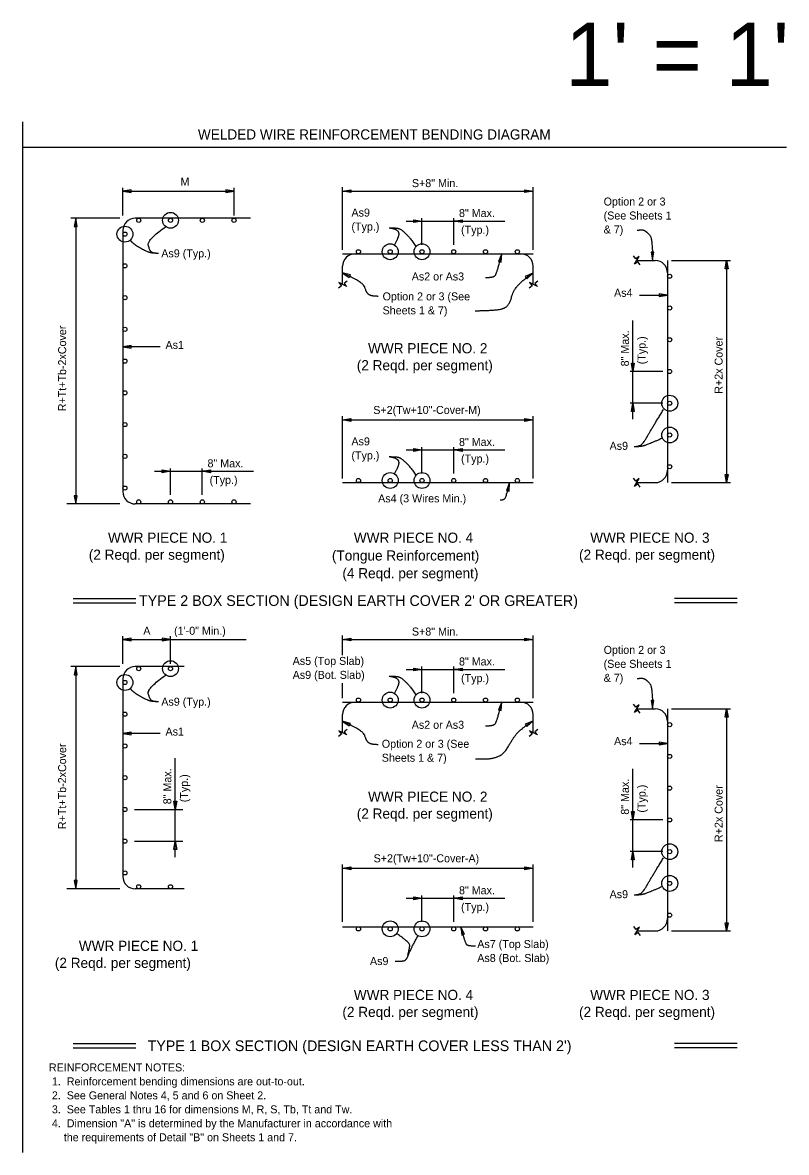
# Model space of a CAD drawing. Extents: x 10340.6 to 10376, y 76398.7 to 76415.8.
# Drawn here: x 10351.54 to 10361.15, y 76401.59 to 76415.83 of the extents above; entities that cross this region are included whole.
import ezdxf

# ---------------------------------------------------------------- set-up
doc = ezdxf.new("R2010")
doc.units = 0
for name, color, linetype in [('AdhocPoint_dp', 7, 'Continuous'), ('PlotBorder_dp', 7, 'Continuous'), ('Rebar', 7, 'Continuous'), ('Rebar_h', 7, 'Continuous'), ('Symbols', 7, 'Continuous')]:
    doc.layers.add(name, color=color, linetype=linetype)

msp = doc.modelspace()

# ---------------------------------------------------------------- linework, layer by layer
at = {"layer": 'PlotBorder_dp'}
for p, q in [((10351.539, 76414.577), (10351.539, 76401.592)), ((10351.539, 76414.259), (10361.155, 76414.259)), ((10352.801, 76413.398), (10352.801, 76413.745)), ((10352.801, 76413.703), (10354.201, 76413.703)), ((10354.201, 76413.398), (10354.201, 76413.745)), ((10355.567, 76412.965), (10355.567, 76413.754)), ((10355.567, 76413.703), (10357.967, 76413.703)), ((10357.967, 76412.965), (10357.967, 76413.754)), ((10352.763, 76413.362), (10352.146, 76413.362)), ((10352.208, 76413.362), (10352.208, 76409.762)), ((10356.567, 76413.029), (10356.567, 76413.361)), ((10356.967, 76413.029), (10356.967, 76413.361)), ((10356.367, 76413.326), (10357.611, 76413.326)), ((10357.068, 76413.326), (10356.967, 76413.326)), ((10359.71, 76412.831), (10360.453, 76412.831)), ((10360.402, 76412.831), (10360.402, 76410.031)), ((10359.307, 76412.392), (10359.66, 76412.392)), ((10359.222, 76410.83), (10359.222, 76412.074)), ((10353.272, 76411.743), (10352.801, 76411.743)), ((10359.222, 76411.531), (10359.222, 76411.431)), ((10359.598, 76411.431), (10359.188, 76411.431)), ((10359.598, 76411.031), (10359.188, 76411.031)), ((10355.567, 76410.081), (10355.567, 76410.87)), ((10355.567, 76410.82), (10357.967, 76410.82)), ((10357.967, 76410.081), (10357.967, 76410.87)), ((10356.367, 76410.443), (10357.611, 76410.443)), ((10356.567, 76410.145), (10356.567, 76410.478)), ((10356.967, 76410.145), (10356.967, 76410.478)), ((10357.068, 76410.443), (10356.967, 76410.443)), ((10353.201, 76410.174), (10354.445, 76410.174)), ((10353.401, 76409.876), (10353.401, 76410.209)), ((10353.801, 76409.876), (10353.801, 76410.209)), ((10353.902, 76410.174), (10353.801, 76410.174)), ((10359.71, 76410.031), (10360.453, 76410.031)), ((10352.763, 76409.762), (10352.096, 76409.762)), ((10352.175, 76408.571), (10352.963, 76408.571)), ((10352.175, 76408.517), (10352.963, 76408.517)), ((10360.535, 76408.571), (10359.748, 76408.571)), ((10360.535, 76408.517), (10359.748, 76408.517)), ((10352.801, 76407.749), (10352.801, 76408.095)), ((10353.401, 76407.749), (10353.401, 76408.095)), ((10355.567, 76407.855), (10355.567, 76408.104)), ((10357.967, 76407.316), (10357.967, 76408.104)), ((10352.801, 76408.054), (10354.354, 76408.054)), ((10355.567, 76408.054), (10357.967, 76408.054)), ((10352.763, 76407.713), (10352.146, 76407.713)), ((10352.208, 76407.713), (10352.208, 76404.913)), ((10356.367, 76407.677), (10357.611, 76407.677)), ((10356.567, 76407.379), (10356.567, 76407.712)), ((10356.967, 76407.379), (10356.967, 76407.712)), ((10357.068, 76407.677), (10356.967, 76407.677)), ((10355.567, 76407.316), (10355.567, 76407.505)), ((10359.71, 76407.181), (10360.453, 76407.181)), ((10360.402, 76407.181), (10360.402, 76404.382)), ((10353.272, 76406.87), (10352.801, 76406.87)), ((10359.307, 76406.743), (10359.66, 76406.743)), ((10353.461, 76405.312), (10353.461, 76406.557)), ((10359.222, 76405.181), (10359.222, 76406.425)), ((10353.461, 76406.014), (10353.461, 76405.913)), ((10352.949, 76405.913), (10353.555, 76405.913)), ((10359.222, 76405.882), (10359.222, 76405.781)), ((10359.598, 76405.781), (10359.188, 76405.781)), ((10352.949, 76405.513), (10353.555, 76405.513)), ((10359.598, 76405.381), (10359.188, 76405.381)), ((10355.567, 76404.495), (10355.567, 76405.221)), ((10355.567, 76405.171), (10357.967, 76405.171)), ((10357.967, 76404.495), (10357.967, 76405.221)), ((10352.763, 76404.913), (10352.096, 76404.913)), ((10356.567, 76404.496), (10356.567, 76404.828)), ((10356.967, 76404.496), (10356.967, 76404.828)), ((10356.367, 76404.794), (10357.611, 76404.794)), ((10357.068, 76404.794), (10356.967, 76404.794)), ((10359.71, 76404.382), (10360.453, 76404.382)), ((10352.175, 76402.962), (10352.963, 76402.962)), ((10360.535, 76402.962), (10359.748, 76402.962)), ((10352.175, 76402.908), (10352.963, 76402.908)), ((10360.535, 76402.908), (10359.748, 76402.908))]:
    msp.add_line(p, q, dxfattribs=at)
for points in [[(10352.801, 76413.703), (10352.905, 76413.686), (10352.905, 76413.721)], [(10354.201, 76413.703), (10354.097, 76413.721), (10354.097, 76413.686)], [(10355.671, 76413.686), (10355.567, 76413.703), (10355.671, 76413.721)], [(10357.863, 76413.721), (10357.967, 76413.703), (10357.863, 76413.686)], [(10352.208, 76413.362), (10352.19, 76413.258), (10352.225, 76413.258)], [(10356.463, 76413.344), (10356.567, 76413.326), (10356.463, 76413.309)], [(10357.071, 76413.309), (10356.967, 76413.326), (10357.071, 76413.344)], [(10357.574, 76412.916), (10357.531, 76412.819), (10357.565, 76412.81)], [(10359.469, 76412.832), (10359.486, 76412.936), (10359.451, 76412.936)], [(10360.385, 76412.726), (10360.402, 76412.831), (10360.42, 76412.726)], [(10355.563, 76412.673), (10355.651, 76412.614), (10355.665, 76412.647)], [(10357.961, 76412.672), (10357.866, 76412.627), (10357.886, 76412.598)], [(10359.66, 76412.392), (10359.555, 76412.41), (10359.555, 76412.375)], [(10352.801, 76411.743), (10352.905, 76411.725), (10352.905, 76411.76)], [(10359.24, 76411.535), (10359.222, 76411.431), (10359.205, 76411.535)], [(10359.205, 76410.926), (10359.222, 76411.031), (10359.24, 76410.926)], [(10355.671, 76410.802), (10355.567, 76410.82), (10355.671, 76410.838)], [(10357.863, 76410.838), (10357.967, 76410.82), (10357.863, 76410.802)], [(10356.463, 76410.461), (10356.567, 76410.443), (10356.463, 76410.425)], [(10357.071, 76410.425), (10356.967, 76410.443), (10357.071, 76410.461)], [(10353.297, 76410.191), (10353.401, 76410.174), (10353.297, 76410.156)], [(10353.905, 76410.156), (10353.801, 76410.174), (10353.905, 76410.191)], [(10360.42, 76410.135), (10360.402, 76410.031), (10360.385, 76410.135)], [(10357.668, 76410.03), (10357.629, 76409.932), (10357.663, 76409.924)], [(10352.208, 76409.762), (10352.225, 76409.866), (10352.19, 76409.866)], [(10352.801, 76408.054), (10352.905, 76408.036), (10352.905, 76408.072)], [(10353.401, 76408.054), (10353.297, 76408.072), (10353.297, 76408.036)], [(10355.671, 76408.036), (10355.567, 76408.054), (10355.671, 76408.072)], [(10357.863, 76408.072), (10357.967, 76408.054), (10357.863, 76408.036)], [(10352.208, 76407.713), (10352.19, 76407.609), (10352.225, 76407.609)], [(10356.463, 76407.695), (10356.567, 76407.677), (10356.463, 76407.659)], [(10357.071, 76407.659), (10356.967, 76407.677), (10357.071, 76407.695)], [(10357.574, 76407.267), (10357.531, 76407.17), (10357.565, 76407.161)], [(10359.469, 76407.183), (10359.486, 76407.287), (10359.451, 76407.287)], [(10360.385, 76407.077), (10360.402, 76407.181), (10360.42, 76407.077)], [(10355.563, 76407.024), (10355.651, 76406.965), (10355.665, 76406.997)], [(10357.964, 76407.027), (10357.867, 76406.986), (10357.886, 76406.956)], [(10352.801, 76406.87), (10352.905, 76406.853), (10352.905, 76406.888)], [(10359.66, 76406.743), (10359.555, 76406.761), (10359.555, 76406.726)], [(10353.479, 76406.017), (10353.461, 76405.913), (10353.444, 76406.017)], [(10359.24, 76405.886), (10359.222, 76405.781), (10359.205, 76405.886)], [(10353.444, 76405.409), (10353.461, 76405.513), (10353.479, 76405.409)], [(10359.205, 76405.277), (10359.222, 76405.381), (10359.24, 76405.277)], [(10355.671, 76405.153), (10355.567, 76405.171), (10355.671, 76405.188)], [(10357.863, 76405.188), (10357.967, 76405.171), (10357.863, 76405.153)], [(10352.208, 76404.913), (10352.225, 76405.017), (10352.19, 76405.017)], [(10356.463, 76404.811), (10356.567, 76404.794), (10356.463, 76404.776)], [(10357.071, 76404.776), (10356.967, 76404.794), (10357.071, 76404.811)], [(10357.054, 76404.435), (10357.067, 76404.33), (10357.101, 76404.34)], [(10360.42, 76404.486), (10360.402, 76404.382), (10360.385, 76404.486)]]:
    msp.add_lwpolyline(points, close=True, dxfattribs=at)
for centre in [(10353.401, 76413.336), (10352.827, 76413.162), (10356.167, 76412.94), (10356.567, 76412.94), (10359.686, 76411.031), (10359.686, 76410.631), (10356.167, 76410.057), (10356.567, 76410.057), (10353.401, 76407.687), (10352.827, 76407.513), (10356.167, 76407.291), (10356.567, 76407.291), (10359.686, 76405.381), (10359.686, 76404.981), (10356.167, 76404.408), (10356.567, 76404.408)]:
    msp.add_circle(centre, 0.1, dxfattribs=at)
for points in [[(10353.249, 76412.919), (10353.177, 76412.919), (10353.137, 76412.959), (10353.106, 76413.086), (10353.336, 76413.255)], [(10356.155, 76413.241), (10356.232, 76413.23), (10356.28, 76413.184), (10356.265, 76413.108), (10356.221, 76413.028)], [(10356.155, 76413.241), (10356.242, 76413.241), (10356.297, 76413.228), (10356.415, 76413.122), (10356.488, 76413.007)], [(10359.278, 76413.21), (10359.344, 76413.224), (10359.406, 76413.183), (10359.469, 76413.108), (10359.469, 76412.832)], [(10353.249, 76412.919), (10353.177, 76412.919), (10353.09, 76412.944), (10352.923, 76413.044), (10352.895, 76413.087)], [(10357.366, 76412.615), (10357.466, 76412.615), (10357.51, 76412.665), (10357.574, 76412.916)], [(10356.014, 76412.378), (10355.914, 76412.378), (10355.859, 76412.443), (10355.83, 76412.554), (10355.563, 76412.673)], [(10357.238, 76412.197), (10357.383, 76412.197), (10357.593, 76412.216), (10357.674, 76412.284), (10357.734, 76412.514), (10357.961, 76412.672)], [(10359.239, 76410.486), (10359.27, 76410.486), (10359.348, 76410.509), (10359.487, 76410.761), (10359.609, 76410.951)], [(10359.239, 76410.486), (10359.322, 76410.486), (10359.415, 76410.514), (10359.586, 76410.59)], [(10356.155, 76410.358), (10356.242, 76410.358), (10356.297, 76410.344), (10356.415, 76410.239), (10356.488, 76410.124)], [(10356.155, 76410.358), (10356.232, 76410.346), (10356.28, 76410.301), (10356.265, 76410.225), (10356.221, 76410.145)], [(10357.551, 76409.812), (10357.596, 76409.812), (10357.631, 76409.857), (10357.668, 76410.03)], [(10353.249, 76407.27), (10353.177, 76407.27), (10353.137, 76407.31), (10353.106, 76407.436), (10353.336, 76407.606)], [(10356.155, 76407.592), (10356.232, 76407.581), (10356.28, 76407.535), (10356.265, 76407.459), (10356.221, 76407.379)], [(10356.155, 76407.592), (10356.242, 76407.592), (10356.297, 76407.579), (10356.415, 76407.473), (10356.488, 76407.358)], [(10359.278, 76407.561), (10359.344, 76407.575), (10359.406, 76407.534), (10359.469, 76407.459), (10359.469, 76407.183)], [(10353.249, 76407.27), (10353.177, 76407.27), (10353.09, 76407.295), (10352.923, 76407.395), (10352.895, 76407.438)], [(10357.366, 76406.966), (10357.466, 76406.966), (10357.51, 76407.016), (10357.574, 76407.267)], [(10356.014, 76406.729), (10355.914, 76406.729), (10355.859, 76406.794), (10355.83, 76406.905), (10355.563, 76407.024)], [(10357.24, 76406.552), (10357.337, 76406.552), (10357.455, 76406.552), (10357.605, 76406.615), (10357.703, 76406.795), (10357.805, 76406.926), (10357.964, 76407.027)], [(10359.239, 76404.837), (10359.27, 76404.837), (10359.348, 76404.86), (10359.487, 76405.112), (10359.609, 76405.302)], [(10359.239, 76404.837), (10359.322, 76404.837), (10359.415, 76404.865), (10359.586, 76404.941)], [(10357.24, 76404.191), (10357.16, 76404.191), (10357.123, 76404.21), (10357.081, 76404.345), (10357.054, 76404.435)], [(10356.23, 76404), (10356.306, 76404), (10356.372, 76404.013), (10356.417, 76404.14), (10356.516, 76404.322)], [(10356.388, 76404.075), (10356.413, 76404.167), (10356.413, 76404.235), (10356.252, 76404.347)]]:
    msp.add_open_spline(points, degree=2, dxfattribs=at)
at = {"layer": 'Rebar'}
for p, q in [((10354.408, 76413.362), (10352.957, 76413.362)), ((10352.801, 76413.206), (10352.801, 76409.918)), ((10355.567, 76412.914), (10357.967, 76412.914)), ((10359.66, 76412.831), (10359.66, 76410.031)), ((10355.567, 76410.031), (10357.967, 76410.031)), ((10354.408, 76409.762), (10352.957, 76409.762)), ((10353.573, 76407.713), (10352.957, 76407.713)), ((10352.801, 76407.557), (10352.801, 76405.069)), ((10355.567, 76407.265), (10357.967, 76407.265)), ((10359.66, 76407.181), (10359.66, 76404.382)), ((10353.573, 76404.913), (10352.957, 76404.913)), ((10355.567, 76404.434), (10357.967, 76404.434))]:
    msp.add_line(p, q, dxfattribs=at)
for centre in [(10353.001, 76413.336), (10353.401, 76413.336), (10353.801, 76413.336), (10354.201, 76413.336), (10352.827, 76413.162), (10355.767, 76412.94), (10356.167, 76412.94), (10356.567, 76412.94), (10356.967, 76412.94), (10357.367, 76412.94), (10357.767, 76412.94), (10352.827, 76412.762), (10359.686, 76412.631), (10352.827, 76412.362), (10359.686, 76412.231), (10352.827, 76411.962), (10359.686, 76411.831), (10352.827, 76411.562), (10359.686, 76411.431), (10352.827, 76411.162), (10359.686, 76411.031), (10352.827, 76410.762), (10359.686, 76410.631), (10352.827, 76410.362), (10359.686, 76410.231), (10355.767, 76410.057), (10356.167, 76410.057), (10356.567, 76410.057), (10356.967, 76410.057), (10357.367, 76410.057), (10357.767, 76410.057), (10352.827, 76409.962), (10352.827, 76409.962), (10353.001, 76409.788), (10353.401, 76409.788), (10353.801, 76409.788), (10354.201, 76409.788), (10353.001, 76407.687), (10353.401, 76407.687), (10352.827, 76407.513), (10355.767, 76407.291), (10356.167, 76407.291), (10356.567, 76407.291), (10356.967, 76407.291), (10357.367, 76407.291), (10357.767, 76407.291), (10352.827, 76407.113), (10359.686, 76406.981), (10352.827, 76406.713), (10359.686, 76406.581), (10352.827, 76406.313), (10359.686, 76406.181), (10352.827, 76405.913), (10359.686, 76405.781), (10352.827, 76405.513), (10359.686, 76405.381), (10352.827, 76405.113), (10353.001, 76404.939), (10353.401, 76404.939), (10359.686, 76404.981), (10359.686, 76404.581), (10355.767, 76404.408), (10356.167, 76404.408), (10356.567, 76404.408), (10356.967, 76404.408), (10357.367, 76404.408), (10357.767, 76404.408)]:
    msp.add_circle(centre, 0.026, dxfattribs=at)
for centre, start, end in [((10352.957, 76413.206), 90, 180), ((10352.957, 76409.918), 180, 270), ((10352.957, 76407.557), 90, 180), ((10352.957, 76405.069), 180, 270)]:
    msp.add_arc(centre, 0.156, start, end, dxfattribs=at)
at = {"layer": 'Rebar_h'}
for p, q in [((10359.277, 76412.831), (10359.503, 76412.831)), ((10355.567, 76412.531), (10355.567, 76412.758)), ((10357.967, 76412.531), (10357.967, 76412.758)), ((10359.277, 76410.031), (10359.503, 76410.031)), ((10355.567, 76406.882), (10355.567, 76407.109)), ((10357.967, 76406.882), (10357.967, 76407.109)), ((10359.277, 76407.181), (10359.503, 76407.181)), ((10359.277, 76404.382), (10359.503, 76404.382))]:
    msp.add_line(p, q, dxfattribs=at)
for centre, start, end in [((10355.724, 76412.758), 90, 180), ((10357.811, 76412.758), 0, 90), ((10359.503, 76412.674), 360, 90), ((10359.503, 76410.187), 270, 360), ((10355.724, 76407.109), 90, 180), ((10357.811, 76407.109), 0, 90), ((10359.503, 76407.025), 360, 90), ((10359.503, 76404.538), 270, 360)]:
    msp.add_arc(centre, 0.156, start, end, dxfattribs=at)
at = {"layer": 'Symbols'}
for points in [[(10359.313, 76412.774), (10359.285, 76412.813), (10359.243, 76412.783), (10359.3, 76412.88), (10359.258, 76412.85), (10359.23, 76412.889)], [(10355.625, 76412.571), (10355.588, 76412.54), (10355.62, 76412.5), (10355.52, 76412.552), (10355.553, 76412.512), (10355.515, 76412.482)], [(10358.025, 76412.571), (10357.988, 76412.54), (10358.02, 76412.5), (10357.92, 76412.552), (10357.953, 76412.512), (10357.915, 76412.482)], [(10359.313, 76409.975), (10359.285, 76410.014), (10359.243, 76409.983), (10359.3, 76410.081), (10359.258, 76410.05), (10359.23, 76410.089)], [(10359.313, 76407.125), (10359.285, 76407.164), (10359.243, 76407.134), (10359.3, 76407.231), (10359.258, 76407.201), (10359.23, 76407.24)], [(10355.625, 76406.921), (10355.588, 76406.891), (10355.62, 76406.851), (10355.52, 76406.903), (10355.553, 76406.863), (10355.515, 76406.832)], [(10358.025, 76406.921), (10357.988, 76406.891), (10358.02, 76406.851), (10357.92, 76406.903), (10357.953, 76406.863), (10357.915, 76406.832)], [(10359.319, 76404.325), (10359.29, 76404.364), (10359.248, 76404.333), (10359.305, 76404.431), (10359.263, 76404.4), (10359.235, 76404.439)]]:
    msp.add_lwpolyline(points, dxfattribs=at)

# ---------------------------------------------------------------- texts
at = {"layer": 'AdhocPoint_dp'}
for s, height, p in [("1' = 1'", 0.8, (10358.371, 76415.027)), ('WELDED WIRE REINFORCEMENT BENDING DIAGRAM', 0.128, (10353.746, 76414.354)), ('M', 0.101, (10353.526, 76413.773)), ('Option 2 or 3 ', 0.1008, (10358.854, 76413.522)), ('As9', 0.1008, (10355.679, 76413.383)), ('(See Sheets 1 ', 0.1008, (10358.854, 76413.346)), ('(Typ.)', 0.1008, (10355.679, 76413.207)), ('(Typ.)', 0.1008, (10357.059, 76413.166)), ('& 7)', 0.1008, (10358.854, 76413.17)), ('As9 (Typ.)', 0.1008, (10353.285, 76412.869)), ('As2 or As3', 0.1008, (10356.438, 76412.578)), ('Option 2 or 3 (See ', 0.1008, (10356.071, 76412.327)), ('As4', 0.1008, (10358.985, 76412.372)), ('Sheets 1 & 7)', 0.1008, (10356.071, 76412.151)), ('As1', 0.1008, (10353.338, 76411.716)), ('WWR PIECE NO. 2', 0.128, (10355.888, 76411.66)), ('(2 Reqd. per segment)', 0.128, (10355.746, 76411.446)), ('As9', 0.1008, (10355.679, 76410.5)), ('As9', 0.1008, (10358.929, 76410.444)), ('(Typ.)', 0.1008, (10355.679, 76410.324)), ('(Typ.)', 0.1008, (10357.059, 76410.283)), ('(Typ.)', 0.1008, (10353.893, 76410.014)), ('As4 (3 Wires Min.)', 0.1008, (10356.015, 76409.782)), ('WWR PIECE NO. 1', 0.128, (10352.614, 76409.273)), ('WWR PIECE NO. 4', 0.128, (10355.709, 76409.273)), ('WWR PIECE NO. 3', 0.128, (10358.685, 76409.273)), ('(2 Reqd. per segment)', 0.128, (10352.372, 76409.059)), ('(Tongue Reinforcement)', 0.128, (10355.433, 76409.049)), ('(2 Reqd. per segment)', 0.128, (10358.544, 76409.059)), ('(4 Reqd. per segment)', 0.128, (10355.565, 76408.826)), ("TYPE 2 BOX SECTION (DESIGN EARTH COVER 2' OR GREATER)", 0.1344, (10353.004, 76408.477)), ('(1\'-0" Min.)', 0.1008, (10353.446, 76408.114)), ('A', 0.101, (10353.058, 76408.114)), ('Option 2 or 3 ', 0.1008, (10358.854, 76407.873)), ('As5 (Top Slab)', 0.1008, (10354.939, 76407.734)), ('(See Sheets 1 ', 0.1008, (10358.854, 76407.697)), ('As9 (Bot. Slab)', 0.1008, (10354.939, 76407.558)), ('(Typ.)', 0.1008, (10357.059, 76407.517)), ('& 7)', 0.1008, (10358.854, 76407.521)), ('As9 (Typ.)', 0.1008, (10353.285, 76407.22)), ('As1', 0.1008, (10353.338, 76406.844)), ('As2 or As3', 0.1008, (10356.438, 76406.929)), ('Option 2 or 3 (See ', 0.1008, (10356.061, 76406.69)), ('As4', 0.1008, (10358.985, 76406.723)), ('Sheets 1 & 7)', 0.1008, (10356.061, 76406.514)), ('WWR PIECE NO. 2', 0.128, (10355.888, 76406.01)), ('(2 Reqd. per segment)', 0.128, (10355.746, 76405.797)), ('As9', 0.1008, (10358.929, 76404.795)), ('(Typ.)', 0.1008, (10357.059, 76404.634)), ('WWR PIECE NO. 1', 0.128, (10352.247, 76404.131)), ('As7 (Top Slab)', 0.1008, (10357.263, 76404.167)), ('As8 (Bot. Slab)', 0.1008, (10357.263, 76403.991)), ('(2 Reqd. per segment)', 0.128, (10351.945, 76403.916)), ('As9', 0.1008, (10355.912, 76403.952)), ('WWR PIECE NO. 4', 0.128, (10355.709, 76403.512)), ('WWR PIECE NO. 3', 0.128, (10358.685, 76403.512)), ('(2 Reqd. per segment)', 0.128, (10355.565, 76403.298)), ('(2 Reqd. per segment)', 0.128, (10358.544, 76403.298)), ("TYPE 1 BOX SECTION (DESIGN EARTH COVER LESS THAN 2')", 0.1344, (10353.112, 76402.868)), ('REINFORCEMENT NOTES:', 0.1008, (10351.87, 76402.612)), (' 1.  Reinforcement bending dimensions are out-to-out.', 0.1008, (10351.87, 76402.436)), (' 2.  See General Notes 4, 5 and 6 on Sheet 2.', 0.1008, (10351.87, 76402.26)), (' 3.  See Tables 1 thru 16 for dimensions M, R, S, Tb, Tt and Tw.', 0.1008, (10351.87, 76402.084)), (' 4.  Dimension "A" is determined by the Manufacturer in accordance with ', 0.1008, (10351.87, 76401.908)), ('     the requirements of Detail "B" on Sheets 1 and 7.', 0.1008, (10351.87, 76401.732))]:
    msp.add_text(s, height=height, dxfattribs=at).set_placement(p)
for s, p in [('R+Tt+Tb-2xCover', (10352.087, 76410.93)), ('(Typ.)', (10359.382, 76411.522)), ('R+Tt+Tb-2xCover', (10352.087, 76405.665)), ('(Typ.)', (10353.621, 76406.004)), ('(Typ.)', (10359.382, 76405.873))]:
    msp.add_text(s, height=0.1008, rotation=90, dxfattribs=at).set_placement(p)
at = {"layer": 'PlotBorder_dp'}
for s, p in [('S+8" Min.', (10356.44, 76413.754)), ('8" Max.', (10357.033, 76413.377)), ('S+2(Tw+10"-Cover-M)', (10355.954, 76410.896)), ('8" Max.', (10357.033, 76410.493)), ('8" Max.', (10353.867, 76410.224)), ('S+8" Min.', (10356.44, 76408.104)), ('8" Max.', (10357.033, 76407.727)), ('S+2(Tw+10"-Cover-A)', (10355.958, 76405.247)), ('8" Max.', (10357.033, 76404.844))]:
    msp.add_text(s, height=0.1008, dxfattribs=at).set_placement(p)
for s, p in [('8" Max.', (10359.172, 76411.496)), ('R+2x Cover', (10360.352, 76411.151)), ('8" Max.', (10353.411, 76405.978)), ('8" Max.', (10359.172, 76405.847)), ('R+2x Cover', (10360.352, 76405.502))]:
    msp.add_text(s, height=0.1008, rotation=90, dxfattribs=at).set_placement(p)

doc.saveas('drawing.dxf')
